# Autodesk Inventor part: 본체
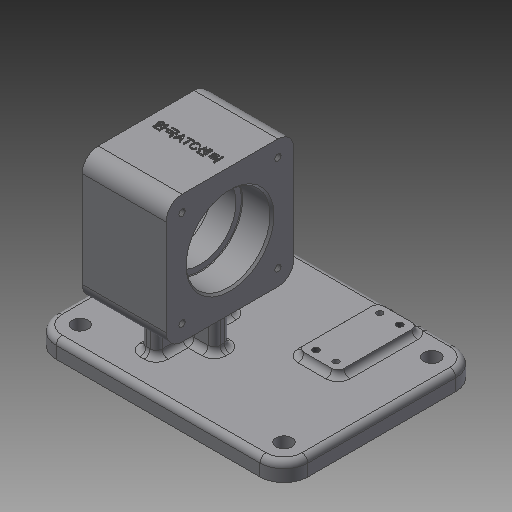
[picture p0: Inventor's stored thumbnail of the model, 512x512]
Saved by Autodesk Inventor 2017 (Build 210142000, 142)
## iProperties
Created: 2019-09
Part Number: 본체
Material: 알루미늄 6061
Document SubType Name: Modeling
Designer: mduedu
Density: 2.71 g/cm^3
Appearance: 기본값
Mass: 636.366 g
Surface Area: 520.125 cm^2
Volume: 234.821 cm^3
Author: mduedu
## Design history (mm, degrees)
sketch "스케치1"
  geometry: L1 (42, -62)-(-84, -62); L2 (-84, -62)-(-84, 36); L3 (-84, 36)-(42, 36); L4 (42, 36)-(42, -62); 1 further point
  constraints: 8 end point, 2 parallel, 1 horizontal, 1 perpendicular
  dimensions: "d0" = 36 distance from line of L3 point (0, 0); "d1" = 98 distance of L1.end L2.end; "d2" = 42 distance from line of L4 point (0, 0); "d3" = 126 distance of L2.end L3.end
extrude "돌출1" new body sketch "스케치1" distance "d4" = 9; taper "d5" = 0 deg
sketch "스케치2"
  geometry: L1 (0, -62)-(0, 36) reference; L2 (27, -32)-(91, -32); L3 (91, -32)-(91, 32); L4 (91, 32)-(27, 32); L5 (27, 32)-(27, -32); L6 (27, -32)-(91, 32); L7 (91, -32)-(27, 32); 3 further points
  constraints: 12 end point, 3 midpoint, 2 parallel, 1 horizontal, 1 horizontal alignment, 1 perpendicular
  dimensions: "d87" = 64 distance of L4.end L3.end; "d88" = 64 distance of L3.end L2.end; "d89" = 59 distance from line of point (59, 0) L1
extrude "돌출2" join sketch "스케치2" stored distance "d8" = 42; taper "d9" = 0 deg
sketch "스케치3"
  geometry: L1 (-17, 4)-(17, 4); L2 (17, 4)-(17, -4); L3 (17, -4)-(-17, -4); L4 (-17, -4)-(-17, 4); L5 (-4, 20)-(4, 20); L6 (4, 20)-(4, -20); L7 (4, -20)-(-4, -20); L8 (-4, -20)-(-4, 20); 5 further points
  constraints: 16 end point, 4 midpoint, 4 parallel, 2 horizontal, 2 horizontal alignment, 2 perpendicular, 2 vertical alignment
  dimensions: "d10" = 8 distance of L5.start L5.end; "d12" = 8 distance of L1.end L2.end; "d13" = 34 distance of L2.end L3.end; "d14" = 40 distance of L5.end L6.end
extrude "돌출3" join sketch "스케치3" stored distance "d15" = 42; taper "d16" = 0 deg
sketch "스케치4"
  geometry: L1 (-32, 91)-(-32, 27) reference; L2 (32, 91)-(-32, 91) reference; L3 (32, 27)-(32, 91) reference; L4 (-32, 27)-(32, 27) reference; C1 r 21 at (0, 59); 3 further points
  constraints: 2 midpoint, 1 centre point, 1 horizontal alignment, 1 vertical alignment
  dimensions: "d17" = 42 diameter of C1
extrude "돌출4" cut sketch "스케치4" distance "d18" = 15; taper "d19" = 0 deg
hole "구멍1" diameter "d22" = 36; stored, may be unused: countersink angle "d26" = 90 deg, drill point angle "d28" = 118 deg; dims "d20" = 10, "d21" = 10, "d23" = 6, "d24" = 4, "d25" = 2, "d27" = 8
fillet "모깎기1" dims "d29" = 0.3
chamfer "모따기1" distance "d30" = 1; stored, may be unused: second distance "d31" = 2, angle "d32" = 45 deg
fillet "모깎기9" dims "d90" = 8
sketch "스케치11"
  geometry: L1 (-24, 27)-(24, 27) reference; L2 (32, 35)-(32, 83) reference; L3 (24, 91)-(-24, 91) reference; L4 (-32, 83)-(-32, 35) reference; C1 r 22 at (0, 59) reference; A1 r 8 centre (-24, 35) between (-32, 35) and (-24, 27) reference; A2 r 8 centre (24, 35) between (24, 27) and (32, 35) reference; A3 r 8 centre (24, 83) between (32, 83) and (24, 91) reference; A4 r 8 centre (-24, 83) between (-24, 91) and (-32, 83) reference; 5 further points
  constraints: 4 coincident
hole "구멍6" sketch "스케치11" at (-24, 83), (24, 83), (24, 35), (-24, 35) diameter "d91" = 3.242; stored, may be unused: countersink angle "d95" = 90 deg, drill point angle "d97" = 118 deg; dims "d92" = 8, "d93" = 4, "d94" = 2, "d96" = 10
fillet "모깎기2" dims "d44" = 12
sketch "스케치6"
  geometry: L1 (-42, 50)-(-42, -24) reference; L2 (-30, -36)-(72, -36) reference; L3 (84, -24)-(84, 50) reference; L4 (72, 62)-(-30, 62) reference; L5 (17, 4)-(17, -4) reference; L6 (17, -4)-(4, -4) reference; L7 (4, -4)-(4, -20) reference; L8 (4, -20)-(-4, -20) reference; L9 (-4, -20)-(-4, -4) reference; L10 (-4, -4)-(-17, -4) reference; L11 (-17, -4)-(-17, 4) reference; L12 (-17, 4)-(-4, 4) reference; L13 (-4, 4)-(-4, 20) reference; L14 (-4, 20)-(4, 20) reference; L15 (4, 20)-(4, 4) reference; L16 (4, 4)-(17, 4) reference; A1 r 12 centre (-30, 50) between (-30, 62) and (-42, 50) reference; A2 r 12 centre (-30, -24) between (-42, -24) and (-30, -36) reference; A3 r 12 centre (72, -24) between (72, -36) and (84, -24) reference; A4 r 12 centre (72, 50) between (84, 50) and (72, 62) reference; 5 further points
  constraints: 4 coincident
hole "구멍3" sketch "스케치6" at (-30, 50), (72, 50), (72, -24), (-30, -24) diameter "d45" = 8; stored, may be unused: countersink angle "d49" = 90 deg, drill point angle "d51" = 118 deg; dims "d46" = 8, "d47" = 4, "d48" = 2, "d50" = 10
sketch "스케치7"
  geometry: L1 (38, 57)-(58, 57); L2 (58, 57)-(58, 17); L3 (58, 17)-(38, 17); L4 (38, 17)-(38, 57); L5 (72, 62)-(-30, 62) reference; 3 further points
  constraints: 8 end point, 2 midpoint, 2 parallel, 1 horizontal, 1 perpendicular
  dimensions: "d52" = 48 horizontal distance of point (48, 57) point (0, 0); "d53" = 20 distance of L1.start L1.end; "d54" = 40 distance of L1.end L2.end; "d55" = 25 distance from line of point (38, 37) L5
extrude "돌출5" join sketch "스케치7" distance "d56" = 3; taper "d57" = 0 deg
fillet "모깎기3" dims "d58" = 3
fillet "모깎기4" dims "d59" = 3
fillet "모깎기5" dims "d60" = 3
fillet "모깎기6" dims "d61" = 3
fillet "모깎기7" dims "d62" = 3
fillet "모깎기8" dims "d63" = 3
sketch "스케치8"
  geometry: L1 (72, 62)-(58.317, 62) reference; L2 (84, -24)-(84, 50) reference; C1 r 1.5 at (43, 53); C2 r 1.5 at (53, 21); 1 further point
  constraints: 2 centre point, 1 equal radius
  dimensions: "d64" = 3 diameter of C1; "d65" = 9 distance from line of C1.centre L1; "d66" = 32 vertical distance of C2.centre C1.centre; "d67" = 10 horizontal distance of C2.centre C1.centre; "d68" = 31 distance from line of L2 C2.centre
hole "구멍4" sketch "스케치8" at (43, 53), (53, 21) diameter "d69" = 3; stored, may be unused: countersink angle "d73" = 90 deg, drill point angle "d75" = 118 deg; dims "d70" = 8, "d71" = 4, "d72" = 2, "d74" = 6
sketch "스케치9"
  geometry: C1 r 1.5 at (43, 53) reference; C2 r 1.5 at (53, 21) reference; 3 further points
  constraints: 2 horizontal alignment, 2 vertical alignment
hole "구멍5" sketch "스케치9" at (53, 53), (43, 21) diameter "d76" = 3.242; stored, may be unused: countersink angle "d80" = 90 deg, drill point angle "d82" = 118 deg; dims "d77" = 6, "d78" = 4, "d79" = 2, "d81" = 8
sketch "스케치10"
  geometry: 2 further points
  constraints: 1 coincident, 1 other
feature "엠보싱1" sketch "스케치10" dims "d0" = 36, "d1" = 98, "d2" = 42, "d3" = 126, "d12" = 8, "d13" = 34, "d85" = 0.5, "d86" = 0
node "솔리드1"
mirror "대칭1"
mirror "대칭2"
node "투영된 루프1"
node "투영된 루프2"
